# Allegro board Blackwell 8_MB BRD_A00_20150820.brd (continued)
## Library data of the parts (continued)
RAM1 RAM2 = BGA253G110115H38: tolerance: 072.H9CCN.000U
RT5101-RT5103 = NTC-402H22-U: tolerance: 69.60011.271
RTC1 SPK1 = 50281-0020N-001: tolerance: 20.F1530.002
SH1 = SKT1603X1424-24: tolerance: 434.05Y08.0001
SH2 = SKT951X1419-24-S: tolerance: 434.05Y0Z.0001
SH4 = SKT520X1447-24: tolerance: 434.05Y0X.0001
SH5 = SKT560X460-24: tolerance: 434.05Y0V.0001
SPR1-SPR3 = SPR5128H111: tolerance: 34.4YW18.001
SPR4 = SPR4013-1H75: tolerance: 34.16M01.001
TP1 = 51651-01001-001: tolerance: 020.K0147.0010
TP401 TP601 TP701 TP702 TP801-TP805 TP1601 TP1602 TP1707 TP1711-TP1713 TP1715 TP1717 TP1719 TP1720 TP2001 TP2401 TP2905-TP2910 TP2912 TP2913 TP2916 TP2918 TP2919 TP3001-TP3003 TP3005 TP3006 TP3901-TP3903 TP4002 TP4101 TP4501-TP4506 TP5101-TP5113 TP5401-TP5405 TP5601 TP5602 = TPAD14-OP: tolerance: ZZ.PAD14.001
U701 U1706 U1708-U1710 U2501 U3402 U4002 U4302 U4501 U4901 U5706 U5709 = SC70-6H44: tolerance: 84.UM6K1.B3F
U1702 U1707 U4301 = XSON8-1410H20: tolerance: 73.00102.A21
U1703 U1705 U5101 = CSP4J076H20: tolerance: 74.70533.03Z
U1704 = BGA169D1111H56: tolerance: 071.01633.000U
U2001 = QFN48J6-G465H40: tolerance: 071.05672.0003
U2901 = BGA96G60-1H40: tolerance: 074.65982.007Z
U2903 = DFN8A5060-G435345H32: tolerance: 72.25Q16.K01
U3101 = QFN28-G4121H32: tolerance: 071.03460.0003
U3102 = QFN48-G5D8H40: tolerance: 71.75130.003
U3401 U3403 = DFN4G1216-GD91D55H24: tolerance: 74.32402.093
U4101 = QFN20-G1D75H24: tolerance: 74.09500.0B3
U4401 = QFN24G4-G2D8H32: tolerance: 74.08556.AE3
U4602 = SSOIC8H44: tolerance: 73.01G74.0HB
U4603 = SC70-5H44: tolerance: 74.00348.A1F
U5202 = QFN10G2020-1H32: tolerance: 074.07066.0073
U5401 = DFN6G1D5H32: tolerance: 074.0G601.0073
U5407 = QFN24-G2D25H40: tolerance: 71.02232.003
U5702 = QFN32G5-G3D6H32: tolerance: 071.00650.0A03
U5707 U5708 = DFN10G2510H22: tolerance: 075.01043.0073
WC3708 = C0201H13: tolerance: 78.2R2B2.1SLRL
WC3710 = C0201H13: tolerance: 78.3R374.1SL
WU3701 = LGA100G1612-G8PH75: tolerance: 054.03042.0001
X701 = S-OSC4-2520-3H40: tolerance: 082.30001.0101
X703 X1701 = SMD49-3215-0713H36: tolerance: 082.30003.0221
XDP1 = AXT340124: tolerance: 20.F1412.040

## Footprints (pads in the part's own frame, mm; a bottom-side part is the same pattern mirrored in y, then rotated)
0R0201-PAD
  custom 0.076x0.076 smd: 1(0,0.279) 2(0,-0.279)
0R0402-PAD
  custom 0.127x0.127 smd: 1(0,0.432) 2(0,-0.432)
0R0603-PAD-1-U
  custom 0.254x0.254 smd: 1(0,0.66) 2(0,-0.66)
2SJ3108-028111F
  oval 1.27x2.032 hole 0.61x1.321: 1(-4.5,7.6) 2(-4.5,2.6) 6(4.5,2.4) MS(4.5,5)
  oval 1.27x1.854 hole 0.61x1.321: 3(-4.5,0) 4(4.5,0)
  oval 1.27x1.93 hole 0.61x1.219: 5(4.5,8.15)
20449-001E
  rect 0.61x0.559 smd: 1(0,-0.971)
  rect 0.508x0.508 smd: 2(0,0.996)
  rect 0.584x1.575 smd: 3(-0.958,0) 4(0.958,0)
50281-0020N-001
  rect 0.813x1.448 smd: 1(0.625,4.124) 2(-0.625,4.124)
  rect 1.346x1.6 smd: 3(2.525,0) 4(-2.525,0)
50521-01001-001
  rect 0.305x0.813 smd: 1(2.25,2.5) 2(1.75,2.5) 3(1.25,2.5) 4(0.75,2.5) 5(0.25,2.5) 6(-0.25,2.5) 7(-0.75,2.5) 8(-1.25,2.5) 9(-1.75,2.5) 10(-2.25,2.5)
  rect 0.406x0.813 smd: 11(3.25,0) 12(-3.25,0)
51483-00801-001
  rect 0.813x1.905 smd: 1(-4.375,4.925) 2(-3.125,4.925) 3(-1.875,4.925) 4(-0.625,4.925) 5(0.625,4.925) 6(1.875,4.925) 7(3.125,4.925) 8(4.375,4.925)
  rect 1.295x3.353 smd: 9(-7.225,0) 10(7.225,0)
51548-01541-W01
  rect 0.305x1.295 smd: 1(-3.5,3.05) 2(-3,3.05) 3(-2.5,3.05) 4(-2,3.05) 5(-1.5,3.05) 6(-1,3.05) 7(-0.5,3.05) 8(0,3.05) 9(0.5,3.05) 10(1,3.05) 11(1.5,3.05) 12(2,3.05) 13(2.5,3.05) 14(3,3.05) 15(3.5,3.05)
  rect 2.159x2.21 smd: 16(-5.825,0) 17(5.825,0)
51651-01001-001
  rect 0.305x0.813 smd: 1(-2.25,2.5) 2(-1.75,2.5) 3(-1.25,2.5) 4(-0.75,2.5) 5(-0.25,2.5) 6(0.25,2.5) 7(0.75,2.5) 8(1.25,2.5) 9(1.75,2.5) 10(2.25,2.5)
  rect 0.457x0.813 smd: 11(-3.465,0) 12(3.465,0)
503398-0891
  rect 0.711x1.092 smd: 1(-3.21,0.015) 2(-2.11,0.015) 3(-1.01,0.015) 4(0.09,0.015) 5(1.19,0.015) 6(2.29,0.015) 7(3.39,0.015) 8(4.49,0.015)
  rect 1.143x1.829 smd: 9(-7.089,0)
  rect 0.711x3.327 smd: 10(-7.305,-11.252) 13(5.644,-11.252)
  rect 0.889x0.94 smd: 11(-5,-12.445)
  rect 1.041x0.787 smd: 12(-0.739,-12.522)
  rect 0.864x2.794 smd: 14(5.568,-0.483)
AA077
  rect 0.508x1.6 smd: 1(-1.55,0) 2(1.55,0)
AS0BC56-R15BB-7H-U
  round 0.254 hole 1.168 unplated: (-11,0)
  round 0.254 hole 1.651 unplated: (11,0)
  round 0.711 hole 0.457: 1(9.25,-0.5) 3(8.75,-1.3) 5(8.25,-0.5) 7(7.75,-1.3) 9(7.25,-0.5) 11(6.75,-1.3) 21(4.25,-0.5) 23(3.75,-1.3) 25(3.25,-0.5) 27(2.75,-1.3) 29(2.25,-0.5) 31(1.75,-1.3) 33(1.25,-0.5) 35(0.75,-1.3) 37(0.25,-0.5) 39(-0.25,-1.3) 41(-0.75,-0.5) 43(-1.25,-1.3) 45(-1.75,-0.5) 47(-2.25,-1.3) 49(-2.75,-0.5) 51(-3.25,-1.3) 53(-3.75,-0.5) 55(-4.25,-1.3) 57(-4.75,-0.5) 59(-5.25,-1.3) 61(-5.75,-0.5) 63(-6.25,-1.3) 65(-6.75,-0.5) 67(-7.25,-1.3) 69(-7.75,-0.5) 71(-8.25,-1.3) 73(-8.75,-0.5) 75(-9.25,-1.3)
  rect 0.305x1.499 smd: 2(9,1.55) 4(8.5,1.55) 6(8,1.55) 8(7.5,1.55) 10(7,1.55) 20(4.5,1.55) 22(4,1.55) 24(3.5,1.55) 26(3,1.55) 28(2.5,1.55) 30(2,1.55) 32(1.5,1.55) 34(1,1.55) 36(0.5,1.55) 38(0,1.55) 40(-0.5,1.55) 42(-1,1.55) 44(-1.5,1.55) 46(-2,1.55) 48(-2.5,1.55) 50(-3,1.55) 52(-3.5,1.55) 54(-4,1.55) 56(-4.5,1.55) 58(-5,1.55) 60(-5.5,1.55) 62(-6,1.55) 64(-6.5,1.55) 66(-7,1.55) 68(-7.5,1.55) 70(-8,1.55) 72(-8.5,1.55) 74(-9,1.55)
  rect 1.194x2.743 smd: 76(-11.385,-4.97) 77(11.385,-4.97)
AXT340124
  rect 0.203x0.737 smd: 1(3.8,1.668) 2(3.8,-1.668) 3(3.4,1.668) 4(3.4,-1.668) 5(3,1.668) 6(3,-1.668) 7(2.6,1.668) 8(2.6,-1.668) 9(2.2,1.668) 10(2.2,-1.668) 11(1.8,1.668) 12(1.8,-1.668) 13(1.4,1.668) 14(1.4,-1.668) 15(1,1.668) 16(1,-1.668) 17(0.6,1.668) 18(0.6,-1.668) 19(0.2,1.668) 20(0.2,-1.668) 21(-0.2,1.668) 22(-0.2,-1.668) 23(-0.6,1.668) 24(-0.6,-1.668) 25(-1,1.668) 26(-1,-1.668) 27(-1.4,1.668) 28(-1.4,-1.668) 29(-1.8,1.668) 30(-1.8,-1.668) 31(-2.2,1.668) 32(-2.2,-1.668) 33(-2.6,1.668) 34(-2.6,-1.668) 35(-3,1.668) 36(-3,-1.668) 37(-3.4,1.668) 38(-3.4,-1.668) 39(-3.8,1.668) 40(-3.8,-1.668)
  rect 0.711x1.118 smd: 41(4.75,1.459) 42(4.75,-1.459) 43(-4.75,1.459) 44(-4.75,-1.459)
BGA96G60-1H40
  round 0.356 smd: A1(-2.5,2.5) A2(-2,2.5) A3(-1.5,2.5) A4(-1,2.5) A5(-0.5,2.5) A6(0,2.5) A7(0.5,2.5) A8(1,2.5) A9(1.5,2.5) A10(2,2.5) A11(2.5,2.5) B1(-2.5,2) B2(-2,2) B3(-1.5,2) B4(-1,2) B5(-0.5,2) B6(0,2) B7(0.5,2) B8(1,2) B9(1.5,2) B10(2,2) B11(2.5,2) C1(-2.5,1.5) C2(-2,1.5) C10(2,1.5) C11(2.5,1.5) D1(-2.5,1) D2(-2,1) D5(-0.5,1) D6(0,1) D7(0.5,1) D8(1,1) D10(2,1) D11(2.5,1) E1(-2.5,0.5) E2(-2,0.5) E4(-1,0.5) E5(-0.5,0.5) E6(0,0.5) E7(0.5,0.5) E8(1,0.5) E10(2,0.5) E11(2.5,0.5) F1(-2.5,0) F2(-2,0) F4(-1,0) F5(-0.5,0) F6(0,0) F7(0.5,0) F8(1,0) F10(2,0) F11(2.5,0) G1(-2.5,-0.5) G2(-2,-0.5) G4(-1,-0.5) G5(-0.5,-0.5) G6(0,-0.5) G7(0.5,-0.5) G8(1,-0.5) G10(2,-0.5) G11(2.5,-0.5) H1(-2.5,-1) H2(-2,-1) H4(-1,-1) H5(-0.5,-1) H6(0,-1) H7(0.5,-1) H8(1,-1) H10(2,-1) H11(2.5,-1) J1(-2.5,-1.5) J2(-2,-1.5) J10(2,-1.5) J11(2.5,-1.5) K1(-2.5,-2) K2(-2,-2) K3(-1.5,-2) K4(-1,-2) K5(-0.5,-2) K6(0,-2) K7(0.5,-2) K8(1,-2) K9(1.5,-2) K10(2,-2) K11(2.5,-2) L1(-2.5,-2.5) L2(-2,-2.5) L3(-1.5,-2.5) L4(-1,-2.5) L5(-0.5,-2.5) L6(0,-2.5) L7(0.5,-2.5) L8(1,-2.5) L9(1.5,-2.5) L10(2,-2.5) L11(2.5,-2.5)
BGA153G115130-1H40
  round 0.356 smd: A1(-3.25,3.25) A2(-2.75,3.25) A3(-2.25,3.25) A4(-1.75,3.25) A5(-1.25,3.25) A6(-0.75,3.25) A7(-0.25,3.25) A8(0.25,3.25) A9(0.75,3.25) A10(1.25,3.25) A11(1.75,3.25) A12(2.25,3.25) A13(2.75,3.25) A14(3.25,3.25) B1(-3.25,2.75) B2(-2.75,2.75) B3(-2.25,2.75) B4(-1.75,2.75) B5(-1.25,2.75) B6(-0.75,2.75) B7(-0.25,2.75) B8(0.25,2.75) B9(0.75,2.75) B10(1.25,2.75) B11(1.75,2.75) B12(2.25,2.75) B13(2.75,2.75) B14(3.25,2.75) C1(-3.25,2.25) C2(-2.75,2.25) C3(-2.25,2.25) C4(-1.75,2.25) C5(-1.25,2.25) C6(-0.75,2.25) C7(-0.25,2.25) C8(0.25,2.25) C9(0.75,2.25) C10(1.25,2.25) C11(1.75,2.25) C12(2.25,2.25) C13(2.75,2.25) C14(3.25,2.25) D1(-3.25,1.75) D2(-2.75,1.75) D3(-2.25,1.75) D4(-1.75,1.75) D12(2.25,1.75) D13(2.75,1.75) D14(3.25,1.75) E1(-3.25,1.25) E2(-2.75,1.25) E3(-2.25,1.25) E5(-1.25,1.25) E6(-0.75,1.25) E7(-0.25,1.25) E8(0.25,1.25) E9(0.75,1.25) E10(1.25,1.25) E12(2.25,1.25) E13(2.75,1.25) E14(3.25,1.25) F1(-3.25,0.75) F2(-2.75,0.75) F3(-2.25,0.75) F5(-1.25,0.75) F10(1.25,0.75) F12(2.25,0.75) F13(2.75,0.75) F14(3.25,0.75) G1(-3.25,0.25) G2(-2.75,0.25) G3(-2.25,0.25) G5(-1.25,0.25) G10(1.25,0.25) G12(2.25,0.25) G13(2.75,0.25) G14(3.25,0.25) H1(-3.25,-0.25) H2(-2.75,-0.25) H3(-2.25,-0.25) H5(-1.25,-0.25) H10(1.25,-0.25) H12(2.25,-0.25) H13(2.75,-0.25) H14(3.25,-0.25) J1(-3.25,-0.75) J2(-2.75,-0.75) J3(-2.25,-0.75) J5(-1.25,-0.75) J10(1.25,-0.75) J12(2.25,-0.75) J13(2.75,-0.75) J14(3.25,-0.75) K1(-3.25,-1.25) K2(-2.75,-1.25) K3(-2.25,-1.25) K5(-1.25,-1.25) K6(-0.75,-1.25) K7(-0.25,-1.25) K8(0.25,-1.25) K9(0.75,-1.25) K10(1.25,-1.25) K12(2.25,-1.25) K13(2.75,-1.25) K14(3.25,-1.25) L1(-3.25,-1.75) L2(-2.75,-1.75) L3(-2.25,-1.75) L12(2.25,-1.75) L13(2.75,-1.75) L14(3.25,-1.75) M1(-3.25,-2.25) M2(-2.75,-2.25) M3(-2.25,-2.25) M4(-1.75,-2.25) M5(-1.25,-2.25) M6(-0.75,-2.25) M7(-0.25,-2.25) M8(0.25,-2.25) M9(0.75,-2.25) M10(1.25,-2.25) M11(1.75,-2.25) M12(2.25,-2.25) M13(2.75,-2.25) M14(3.25,-2.25) N1(-3.25,-2.75) N2(-2.75,-2.75) N3(-2.25,-2.75) N4(-1.75,-2.75) N5(-1.25,-2.75) N6(-0.75,-2.75) N7(-0.25,-2.75) N8(0.25,-2.75) N9(0.75,-2.75) N10(1.25,-2.75) N11(1.75,-2.75) N12(2.25,-2.75) N13(2.75,-2.75) N14(3.25,-2.75) P1(-3.25,-3.25) P2(-2.75,-3.25) P3(-2.25,-3.25) P4(-1.75,-3.25) P5(-1.25,-3.25) P6(-0.75,-3.25) P7(-0.25,-3.25) P8(0.25,-3.25) P9(0.75,-3.25) P10(1.25,-3.25) P11(1.75,-3.25) P12(2.25,-3.25) P13(2.75,-3.25) P14(3.25,-3.25)
BGA169D1111H56
  round 0.406 smd: A1(-4.8,4.8) A2(-4,4.8) A3(-3.2,4.8) A11(3.2,4.8) A12(4,4.8) A13(4.8,4.8) B1(-4.8,4) B2(-4,4) B3(-3.2,4) B11(3.2,4) B12(4,4) B13(4.8,4) C1(-4.8,3.2) C2(-4,3.2) C3(-3.2,3.2) C11(3.2,3.2) C12(4,3.2) C13(4.8,3.2) L1(-4.8,-3.2) L2(-4,-3.2) L3(-3.2,-3.2) L11(3.2,-3.2) L12(4,-3.2) L13(4.8,-3.2) M1(-4.8,-4) M2(-4,-4) M3(-3.2,-4) M11(3.2,-4) M12(4,-4) M13(4.8,-4) N1(-4.8,-4.8) N2(-4,-4.8) N3(-3.2,-4.8) N11(3.2,-4.8) N12(4,-4.8) N13(4.8,-4.8)
  round 0.356 smd: A4(-2.4,4.8) A5(-1.6,4.8) A6(-0.8,4.8) A7(0,4.8) A8(0.8,4.8) A9(1.6,4.8) A10(2.4,4.8) B4(-2.4,4) B5(-1.6,4) B6(-0.8,4) B7(0,4) B8(0.8,4) B9(1.6,4) B10(2.4,4) C4(-2.4,3.2) C5(-1.6,3.2) C6(-0.8,3.2) C7(0,3.2) C8(0.8,3.2) C9(1.6,3.2) C10(2.4,3.2) D1(-4.8,2.4) D2(-4,2.4) D3(-3.2,2.4) D4(-2.4,2.4) D5(-1.6,2.4) D6(-0.8,2.4) D7(0,2.4) D8(0.8,2.4) D9(1.6,2.4) D10(2.4,2.4) D11(3.2,2.4) D12(4,2.4) D13(4.8,2.4) E1(-4.8,1.6) E2(-4,1.6) E3(-3.2,1.6) E4(-2.4,1.6) E5(-1.6,1.6) E6(-0.8,1.6) E7(0,1.6) E8(0.8,1.6) E9(1.6,1.6) E10(2.4,1.6) E11(3.2,1.6) E12(4,1.6) E13(4.8,1.6) F1(-4.8,0.8) F2(-4,0.8) F3(-3.2,0.8) F4(-2.4,0.8) F5(-1.6,0.8) F6(-0.8,0.8) F7(0,0.8) F8(0.8,0.8) F9(1.6,0.8) F10(2.4,0.8) F11(3.2,0.8) F12(4,0.8) F13(4.8,0.8) G1(-4.8,0) G2(-4,0) G3(-3.2,0) G4(-2.4,0) G5(-1.6,0) G6(-0.8,0) G7(0,0) G8(0.8,0) G9(1.6,0) G10(2.4,0) G11(3.2,0) G12(4,0) G13(4.8,0) H1(-4.8,-0.8) H2(-4,-0.8) H3(-3.2,-0.8) H4(-2.4,-0.8) H5(-1.6,-0.8) H6(-0.8,-0.8) H7(0,-0.8) H8(0.8,-0.8) H9(1.6,-0.8) H10(2.4,-0.8) H11(3.2,-0.8) H12(4,-0.8) H13(4.8,-0.8) J1(-4.8,-1.6) J2(-4,-1.6) J3(-3.2,-1.6) J4(-2.4,-1.6) J5(-1.6,-1.6) J6(-0.8,-1.6) J7(0,-1.6) J8(0.8,-1.6) J9(1.6,-1.6) J10(2.4,-1.6) J11(3.2,-1.6) J12(4,-1.6) J13(4.8,-1.6) K1(-4.8,-2.4) K2(-4,-2.4) K3(-3.2,-2.4) K4(-2.4,-2.4) K5(-1.6,-2.4) K6(-0.8,-2.4) K7(0,-2.4) K8(0.8,-2.4) K9(1.6,-2.4) K10(2.4,-2.4) K11(3.2,-2.4) K12(4,-2.4) K13(4.8,-2.4) L4(-2.4,-3.2) L5(-1.6,-3.2) L6(-0.8,-3.2) L7(0,-3.2) L8(0.8,-3.2) L9(1.6,-3.2) L10(2.4,-3.2) M4(-2.4,-4) M5(-1.6,-4) M6(-0.8,-4) M7(0,-4) M8(0.8,-4) M9(1.6,-4) M10(2.4,-4) N4(-2.4,-4.8) N5(-1.6,-4.8) N6(-0.8,-4.8) N7(0,-4.8) N8(0.8,-4.8) N9(1.6,-4.8) N10(2.4,-4.8)
BGA224J6D2H25
  round 0.241 smd: A1(-2.8,2.8) A2(-2.4,2.8) A3(-2,2.8) A4(-1.6,2.8) A5(-1.2,2.8) A6(-0.8,2.8) A7(-0.4,2.8) A8(0,2.8) A9(0.4,2.8) A10(0.8,2.8) A11(1.2,2.8) A12(1.6,2.8) A13(2,2.8) A14(2.4,2.8) A15(2.8,2.8) B1(-2.8,2.4) B2(-2.4,2.4) B3(-2,2.4) B4(-1.6,2.4) B5(-1.2,2.4) B6(-0.8,2.4) B7(-0.4,2.4) B8(0,2.4) B9(0.4,2.4) B10(0.8,2.4) B11(1.2,2.4) B12(1.6,2.4) B13(2,2.4) B14(2.4,2.4) B15(2.8,2.4) C1(-2.8,2) C2(-2.4,2) C3(-2,2) C4(-1.6,2) C5(-1.2,2) C6(-0.8,2) C7(-0.4,2) C8(0,2) C9(0.4,2) C10(0.8,2) C11(1.2,2) C12(1.6,2) C13(2,2) C14(2.4,2) C15(2.8,2) D1(-2.8,1.6) D2(-2.4,1.6) D3(-2,1.6) D4(-1.6,1.6) D5(-1.2,1.6) D6(-0.8,1.6) D7(-0.4,1.6) D8(0,1.6) D9(0.4,1.6) D10(0.8,1.6) D11(1.2,1.6) D12(1.6,1.6) D13(2,1.6) D14(2.4,1.6) D15(2.8,1.6) E1(-2.8,1.2) E2(-2.4,1.2) E3(-2,1.2) E4(-1.6,1.2) E5(-1.2,1.2) E6(-0.8,1.2) E7(-0.4,1.2) E8(0,1.2) E9(0.4,1.2) E10(0.8,1.2) E11(1.2,1.2) E12(1.6,1.2) E13(2,1.2) E14(2.4,1.2) E15(2.8,1.2) F1(-2.8,0.8) F2(-2.4,0.8) F3(-2,0.8) F4(-1.6,0.8) F5(-1.2,0.8) F6(-0.8,0.8) F7(-0.4,0.8) F8(0,0.8) F9(0.4,0.8) F10(0.8,0.8) F11(1.2,0.8) F12(1.6,0.8) F13(2,0.8) F14(2.4,0.8) F15(2.8,0.8) G1(-2.8,0.4) G2(-2.4,0.4) G3(-2,0.4) G4(-1.6,0.4) G5(-1.2,0.4) G6(-0.8,0.4) G8(0,0.4) G9(0.4,0.4) G10(0.8,0.4) G11(1.2,0.4) G12(1.6,0.4) G13(2,0.4) G14(2.4,0.4) G15(2.8,0.4) H1(-2.8,0) H2(-2.4,0) H3(-2,0) H4(-1.6,0) H5(-1.2,0) H6(-0.8,0) H7(-0.4,0) H8(0,0) H9(0.4,0) H10(0.8,0) H11(1.2,0) H12(1.6,0) H13(2,0) H14(2.4,0) H15(2.8,0) J1(-2.8,-0.4) J2(-2.4,-0.4) J3(-2,-0.4) J4(-1.6,-0.4) J5(-1.2,-0.4) J6(-0.8,-0.4) J7(-0.4,-0.4) J8(0,-0.4) J9(0.4,-0.4) J10(0.8,-0.4) J11(1.2,-0.4) J12(1.6,-0.4) J13(2,-0.4) J14(2.4,-0.4) J15(2.8,-0.4) K1(-2.8,-0.8) K2(-2.4,-0.8) K3(-2,-0.8) K4(-1.6,-0.8) K5(-1.2,-0.8) K6(-0.8,-0.8) K7(-0.4,-0.8) K8(0,-0.8) K9(0.4,-0.8) K10(0.8,-0.8) K11(1.2,-0.8) K12(1.6,-0.8) K13(2,-0.8) K14(2.4,-0.8) K15(2.8,-0.8) L1(-2.8,-1.2) L2(-2.4,-1.2) L3(-2,-1.2) L4(-1.6,-1.2) L5(-1.2,-1.2) L6(-0.8,-1.2) L7(-0.4,-1.2) L8(0,-1.2) L9(0.4,-1.2) L10(0.8,-1.2) L11(1.2,-1.2) L12(1.6,-1.2) L13(2,-1.2) L14(2.4,-1.2) L15(2.8,-1.2) M1(-2.8,-1.6) M2(-2.4,-1.6) M3(-2,-1.6) M4(-1.6,-1.6) M5(-1.2,-1.6) M6(-0.8,-1.6) M7(-0.4,-1.6) M8(0,-1.6) M9(0.4,-1.6) M10(0.8,-1.6) M11(1.2,-1.6) M12(1.6,-1.6) M13(2,-1.6) M14(2.4,-1.6) M15(2.8,-1.6) N1(-2.8,-2) N2(-2.4,-2) N3(-2,-2) N4(-1.6,-2) N5(-1.2,-2) N6(-0.8,-2) N7(-0.4,-2) N8(0,-2) N9(0.4,-2) N10(0.8,-2) N11(1.2,-2) N12(1.6,-2) N13(2,-2) N14(2.4,-2) N15(2.8,-2) P1(-2.8,-2.4) P2(-2.4,-2.4) P3(-2,-2.4) P4(-1.6,-2.4) P5(-1.2,-2.4) P6(-0.8,-2.4) P7(-0.4,-2.4) P8(0,-2.4) P9(0.4,-2.4) P10(0.8,-2.4) P11(1.2,-2.4) P12(1.6,-2.4) P13(2,-2.4) P14(2.4,-2.4) P15(2.8,-2.4) R1(-2.8,-2.8) R2(-2.4,-2.8) R3(-2,-2.8) R4(-1.6,-2.8) R5(-1.2,-2.8) R6(-0.8,-2.8) R7(-0.4,-2.8) R8(0,-2.8) R9(0.4,-2.8) R10(0.8,-2.8) R11(1.2,-2.8) R12(1.6,-2.8) R13(2,-2.8) R14(2.4,-2.8) R15(2.8,-2.8)
BGA253G110115H38
  round 0.356 smd: A1(-4,4) A2(-3.5,4) A3(-3,4) A4(-2.5,4) A5(-2,4) A6(-1.5,4) A7(-1,4) A8(-0.5,4) A9(0,4) A10(0.5,4) A11(1,4) A12(1.5,4) A13(2,4) A14(2.5,4) A15(3,4) A16(3.5,4) A17(4,4) B1(-4,3.5) B2(-3.5,3.5) B3(-3,3.5) B4(-2.5,3.5) B5(-2,3.5) B6(-1.5,3.5) B7(-1,3.5) B8(-0.5,3.5) B9(0,3.5) B10(0.5,3.5) B11(1,3.5) B12(1.5,3.5) B13(2,3.5) B14(2.5,3.5) B15(3,3.5) B16(3.5,3.5) B17(4,3.5) C1(-4,3) C2(-3.5,3) C3(-3,3) C4(-2.5,3) C5(-2,3) C6(-1.5,3) C7(-1,3) C8(-0.5,3) C9(0,3) C10(0.5,3) C11(1,3) C12(1.5,3) C13(2,3) C14(2.5,3) C15(3,3) C16(3.5,3) C17(4,3) D1(-4,2.5) D2(-3.5,2.5) D3(-3,2.5) D4(-2.5,2.5) D5(-2,2.5) D6(-1.5,2.5) D7(-1,2.5) D8(-0.5,2.5) D9(0,2.5) D10(0.5,2.5) D11(1,2.5) D12(1.5,2.5) D13(2,2.5) D14(2.5,2.5) D15(3,2.5) D16(3.5,2.5) D17(4,2.5) E1(-4,2) E2(-3.5,2) E3(-3,2) E4(-2.5,2) E5(-2,2) E6(-1.5,2) E7(-1,2) E8(-0.5,2) E9(0,2) E10(0.5,2) E11(1,2) E12(1.5,2) E13(2,2) E14(2.5,2) E15(3,2) E16(3.5,2) E17(4,2) F1(-4,1.5) F2(-3.5,1.5) F3(-3,1.5) F4(-2.5,1.5) F5(-2,1.5) F12(1.5,1.5) F13(2,1.5) F14(2.5,1.5) F15(3,1.5) F16(3.5,1.5) F17(4,1.5) G1(-4,1) G2(-3.5,1) G3(-3,1) G4(-2.5,1) G5(-2,1) G12(1.5,1) G13(2,1) G14(2.5,1) G15(3,1) G16(3.5,1) G17(4,1) H1(-4,0.5) H2(-3.5,0.5) H3(-3,0.5) H4(-2.5,0.5) H5(-2,0.5) H12(1.5,0.5) H13(2,0.5) H14(2.5,0.5) H15(3,0.5) H16(3.5,0.5) H17(4,0.5) J1(-4,0) J2(-3.5,0) J3(-3,0) J4(-2.5,0) J5(-2,0) J12(1.5,0) J13(2,0) J14(2.5,0) J15(3,0) J16(3.5,0) J17(4,0) K1(-4,-0.5) K2(-3.5,-0.5) K3(-3,-0.5) K4(-2.5,-0.5) K5(-2,-0.5) K12(1.5,-0.5) K13(2,-0.5) K14(2.5,-0.5) K15(3,-0.5) K16(3.5,-0.5) K17(4,-0.5) L1(-4,-1) L2(-3.5,-1) L3(-3,-1) L4(-2.5,-1) L5(-2,-1) L12(1.5,-1) L13(2,-1) L14(2.5,-1) L15(3,-1) L16(3.5,-1) L17(4,-1) M1(-4,-1.5) M2(-3.5,-1.5) M3(-3,-1.5) M4(-2.5,-1.5) M5(-2,-1.5) M6(-1.5,-1.5) M7(-1,-1.5) M8(-0.5,-1.5) M9(0,-1.5) M10(0.5,-1.5) M11(1,-1.5) M12(1.5,-1.5) M13(2,-1.5) M14(2.5,-1.5) M15(3,-1.5) M16(3.5,-1.5) M17(4,-1.5) N1(-4,-2) N2(-3.5,-2) N3(-3,-2) N4(-2.5,-2) N5(-2,-2) N6(-1.5,-2) N7(-1,-2) N8(-0.5,-2) N9(0,-2) N10(0.5,-2) N11(1,-2) N12(1.5,-2) N13(2,-2) N14(2.5,-2) N15(3,-2) N16(3.5,-2) N17(4,-2) P1(-4,-2.5) P2(-3.5,-2.5) P3(-3,-2.5) P4(-2.5,-2.5) P5(-2,-2.5) P6(-1.5,-2.5) P7(-1,-2.5) P8(-0.5,-2.5) P9(0,-2.5) P10(0.5,-2.5) P11(1,-2.5) P12(1.5,-2.5) P13(2,-2.5) P14(2.5,-2.5) P15(3,-2.5) P16(3.5,-2.5) P17(4,-2.5) R1(-4,-3) R2(-3.5,-3) R3(-3,-3) R4(-2.5,-3) R5(-2,-3) R6(-1.5,-3) R7(-1,-3) R8(-0.5,-3) R9(0,-3) R10(0.5,-3) R11(1,-3) R12(1.5,-3) R13(2,-3) R14(2.5,-3) R15(3,-3) R16(3.5,-3) R17(4,-3) T1(-4,-3.5) T2(-3.5,-3.5) T3(-3,-3.5) T4(-2.5,-3.5) T5(-2,-3.5) T6(-1.5,-3.5) T7(-1,-3.5) T8(-0.5,-3.5) T9(0,-3.5) T10(0.5,-3.5) T11(1,-3.5) T12(1.5,-3.5) T13(2,-3.5) T14(2.5,-3.5) T15(3,-3.5) T16(3.5,-3.5) T17(4,-3.5) U1(-4,-4) U2(-3.5,-4) U3(-3,-4) U4(-2.5,-4) U5(-2,-4) U6(-1.5,-4) U7(-1,-4) U8(-0.5,-4) U9(0,-4) U10(0.5,-4) U11(1,-4) U12(1.5,-4) U13(2,-4) U14(2.5,-4) U15(3,-4) U16(3.5,-4) U17(4,-4)
BGA1380M17-UH41
  round 0.25 smd: A3(7.357,-7.998) A5(6.791,-7.998) A7(6.225,-7.998) A53(-6.225,-7.998) A55(-6.791,-7.998) A57(-7.357,-7.998) AA3(7.357,-2.264) AA5(6.791,-2.264) AA7(6.225,-2.264) AA9(5.659,-2.264) AA11(5.093,-2.264) AA49(-5.093,-2.264) AA51(-5.659,-2.264) AA53(-6.225,-2.264) AA55(-6.791,-2.264) AA57(-7.357,-2.264) AB4(7.074,-1.981) AB6(6.508,-1.981) AB8(5.942,-1.981) AB10(5.376,-1.981) AB12(4.81,-1.981) AB48(-4.81,-1.981) AB50(-5.376,-1.981) AB52(-5.942,-1.981) AB54(-6.508,-1.981) AB56(-7.074,-1.981) AC3(7.357,-1.698) AC5(6.791,-1.698) AC7(6.225,-1.698) AC9(5.659,-1.698) AC11(5.093,-1.698) AC49(-5.093,-1.698) AC51(-5.659,-1.698) AC53(-6.225,-1.698) AC55(-6.791,-1.698) AC57(-7.357,-1.698) AD2(7.715,-1.415) AD4(7.074,-1.415) AD6(6.508,-1.415) AD8(5.942,-1.415) AD10(5.376,-1.415) AD12(4.81,-1.415) AD48(-4.81,-1.415) AD50(-5.376,-1.415) AD52(-5.942,-1.415) AD54(-6.508,-1.415) AD56(-7.074,-1.415) AD58(-7.715,-1.415) AE3(7.394,-1.169) AE5(6.791,-1.132) AE7(6.225,-1.132) AE9(5.659,-1.132) AE11(5.093,-1.132) AE49(-5.093,-1.132) AE51(-5.659,-1.132) AE53(-6.225,-1.132) AE55(-6.791,-1.132) AE57(-7.394,-1.169) AF4(7.074,-0.849) AF6(6.508,-0.849) AF8(5.942,-0.849) AF10(5.376,-0.849) AF12(4.81,-0.849) AF48(-4.81,-0.849) AF50(-5.376,-0.849) AF52(-5.942,-0.849) AF54(-6.508,-0.849) AF56(-7.074,-0.849) AG3(7.394,-0.529) AG5(6.791,-0.566) AG7(6.225,-0.566) AG9(5.659,-0.566) AG11(5.093,-0.566) AG49(-5.093,-0.566) AG51(-5.659,-0.566) AG53(-6.225,-0.566) AG55(-6.791,-0.566) AG57(-7.394,-0.529) AH2(7.715,-0.283) AH4(7.074,-0.283) AH6(6.508,-0.283) AH8(5.942,-0.283) AH10(5.376,-0.283) AH12(4.81,-0.283) AH48(-4.81,-0.283) AH50(-5.376,-0.283) AH52(-5.942,-0.283) AH54(-6.508,-0.283) AH56(-7.074,-0.283) AH58(-7.715,-0.283) AK3(7.357,0) AK5(6.791,0) AK7(6.225,0) AK9(5.659,0) AK11(5.093,0) AK49(-5.093,0) AK51(-5.659,0) AK53(-6.225,0) AK55(-6.791,0) AK57(-7.357,0) AM2(7.715,0.283) AM4(7.074,0.283) AM6(6.508,0.283) AM8(5.942,0.283) AM10(5.376,0.283) AM12(4.81,0.283) AM48(-4.81,0.283) AM50(-5.376,0.283) AM52(-5.942,0.283) AM54(-6.508,0.283) AM56(-7.074,0.283) AM58(-7.715,0.283) AN3(7.394,0.529) AN5(6.791,0.566) AN7(6.225,0.566) AN9(5.659,0.566) AN11(5.093,0.566) AN49(-5.093,0.566) AN51(-5.659,0.566) AN53(-6.225,0.566) AN55(-6.791,0.566) AN57(-7.394,0.529) AP4(7.074,0.849) AP6(6.508,0.849) AP8(5.942,0.849) AP10(5.376,0.849) AP12(4.81,0.849) AP48(-4.81,0.849) AP50(-5.376,0.849) AP52(-5.942,0.849) AP54(-6.508,0.849) AP56(-7.074,0.849) AR3(7.394,1.169) AR5(6.791,1.132) AR7(6.225,1.132) AR9(5.659,1.132) AR11(5.093,1.132) AR49(-5.093,1.132) AR51(-5.659,1.132) AR53(-6.225,1.132) AR55(-6.791,1.132) AR57(-7.394,1.169) AT2(7.715,1.415) AT4(7.074,1.415) AT6(6.508,1.415) AT8(5.942,1.415) AT10(5.376,1.415) AT12(4.81,1.415) AT48(-4.81,1.415) AT50(-5.376,1.415) AT52(-5.942,1.415) AT54(-6.508,1.415) AT56(-7.074,1.415) AT58(-7.715,1.415) AU3(7.357,1.698) AU5(6.791,1.698) AU7(6.225,1.698) AU9(5.659,1.698) AU11(5.093,1.698) AU49(-5.093,1.698) AU51(-5.659,1.698) AU53(-6.225,1.698) AU55(-6.791,1.698) AU57(-7.357,1.698) AV4(7.074,1.981) AV6(6.508,1.981) AV8(5.942,1.981) AV10(5.376,1.981) AV12(4.81,1.981) AV48(-4.81,1.981) AV50(-5.376,1.981) AV52(-5.942,1.981) AV54(-6.508,1.981) AV56(-7.074,1.981) AW3(7.357,2.264) AW5(6.791,2.264) AW7(6.225,2.264) AW9(5.659,2.264) AW11(5.093,2.264) AW49(-5.093,2.264) AW51(-5.659,2.264) AW53(-6.225,2.264) AW55(-6.791,2.264) AW57(-7.357,2.264) AY2(7.715,2.547) AY4(7.074,2.547) AY6(6.508,2.547) AY8(5.942,2.547) AY10(5.376,2.547) AY12(4.81,2.547) AY48(-4.81,2.547) AY50(-5.376,2.547) AY52(-5.942,2.547) AY54(-6.508,2.547) AY56(-7.074,2.547) AY58(-7.715,2.547) B2(7.64,-7.64) B4(7.074,-7.715) B6(6.508,-7.64) B8(5.942,-7.715) B12(4.81,-7.715) B16(3.678,-7.715) B20(2.547,-7.715) B24(1.415,-7.715) B28(0.283,-7.715) B34(-0.849,-7.715) B38(-1.981,-7.715) B42(-3.113,-7.715) B46(-4.244,-7.715) B50(-5.376,-7.715) B54(-6.508,-7.715) B56(-7.074,-7.64) B58(-7.64,-7.64) BA3(7.394,2.792) BA5(6.791,2.83) BA7(6.225,2.83) BA9(5.659,2.83) BA11(5.093,2.83) BA49(-5.093,2.83) BA51(-5.659,2.83) BA53(-6.225,2.83) BA55(-6.791,2.83) BA57(-7.394,2.792) BB4(7.074,3.113) BB6(6.508,3.113) BB8(5.942,3.113) BB10(5.376,3.113) BB12(4.81,3.113) BB48(-4.81,3.113) BB50(-5.376,3.113) BB52(-5.942,3.113) BB54(-6.508,3.113) BB56(-7.074,3.113) BC3(7.394,3.433) BC5(6.791,3.395) BC7(6.225,3.395) BC9(5.659,3.395) BC11(5.093,3.395) BC49(-5.093,3.395) BC51(-5.659,3.395) BC53(-6.225,3.395) BC55(-6.791,3.395) BC57(-7.394,3.433) BD2(7.715,3.678) BD4(7.074,3.678) BD6(6.508,3.678) BD8(5.942,3.678) BD10(5.376,3.678) BD12(4.81,3.678) BD48(-4.81,3.678) BD50(-5.376,3.678) BD52(-5.942,3.678) BD54(-6.508,3.678) BD56(-7.074,3.678) BD58(-7.715,3.678) BE3(7.357,3.961) BE5(6.791,3.961) BE7(6.225,3.961) BE9(5.659,3.961) BE11(5.093,3.961) BE49(-5.093,3.961) BE51(-5.659,3.961) BE53(-6.225,3.961) BE55(-6.791,3.961) BE57(-7.357,3.961) BF4(7.074,4.244) BF6(6.508,4.244) BF8(5.942,4.244) BF10(5.376,4.244) BF12(4.81,4.244) BF48(-4.81,4.244) BF50(-5.376,4.244) BF52(-5.942,4.244) BF54(-6.508,4.244) BF56(-7.074,4.244) BG3(7.357,4.527) BG5(6.791,4.527) BG7(6.225,4.527) BG9(5.659,4.527) BG11(5.093,4.527) BG49(-5.093,4.527) BG51(-5.659,4.527) BG53(-6.225,4.527) BG55(-6.791,4.527) BG57(-7.357,4.527) BH2(7.715,4.81) BH4(7.074,4.81) BH6(6.508,4.81) BH8(5.942,4.81) BH10(5.376,4.81) BH12(4.81,4.81) BH14(4.244,4.81) BH16(3.678,4.81) BH18(3.113,4.81) BH20(2.547,4.81) BH22(1.981,4.81) BH24(1.415,4.81) BH26(0.849,4.81) BH28(0.283,4.81) BH32(-0.283,4.81) BH34(-0.849,4.81) BH36(-1.415,4.81) BH38(-1.981,4.81) BH40(-2.547,4.81) BH42(-3.113,4.81) BH44(-3.678,4.81) BH46(-4.244,4.81) BH48(-4.81,4.81) BH50(-5.376,4.81) BH52(-5.942,4.81) BH54(-6.508,4.81) BH56(-7.074,4.81) BH58(-7.715,4.81) BJ3(7.394,5.056) BJ5(6.791,5.093) BJ7(6.225,5.093) BJ9(5.659,5.093) BJ11(5.093,5.093) BJ13(4.527,5.093) BJ15(3.961,5.093) BJ17(3.395,5.093) BJ19(2.83,5.093) BJ21(2.264,5.093) BJ23(1.698,5.093) BJ25(1.132,5.093) BJ27(0.566,5.093) BJ30(0,5.093) BJ33(-0.566,5.093) BJ35(-1.132,5.093) BJ37(-1.698,5.093) BJ39(-2.264,5.093) BJ41(-2.83,5.093) BJ43(-3.395,5.093) BJ45(-3.961,5.093) BJ47(-4.527,5.093) BJ49(-5.093,5.093) BJ51(-5.659,5.093) BJ53(-6.225,5.093) BJ55(-6.791,5.093) BJ57(-7.394,5.056) BK4(7.074,5.376) BK6(6.508,5.376) BK8(5.942,5.376) BK10(5.376,5.376) BK12(4.81,5.376) BK14(4.244,5.376) BK16(3.678,5.376) BK18(3.113,5.376) BK20(2.547,5.376) BK22(1.981,5.376) BK24(1.415,5.376) BK26(0.849,5.376) BK28(0.283,5.376) BK32(-0.283,5.376) BK34(-0.849,5.376) BK36(-1.415,5.376) BK38(-1.981,5.376) BK40(-2.547,5.376) BK42(-3.113,5.376) BK44(-3.678,5.376) BK46(-4.244,5.376) BK48(-4.81,5.376) BK50(-5.376,5.376) BK52(-5.942,5.376) BK54(-6.508,5.376) BK56(-7.074,5.376) BL3(7.394,5.696) BL5(6.791,5.659) BL7(6.225,5.659) BL9(5.659,5.659) BL11(5.093,5.659) BL13(4.527,5.659) BL15(3.961,5.659) BL17(3.395,5.659) BL19(2.83,5.659) BL21(2.264,5.659) BL23(1.698,5.659) BL25(1.132,5.659) BL27(0.566,5.659) BL30(0,5.659) BL33(-0.566,5.659) BL35(-1.132,5.659) BL37(-1.698,5.659) BL39(-2.264,5.659) BL41(-2.83,5.659) BL43(-3.395,5.659) BL45(-3.961,5.659) BL47(-4.527,5.659) BL49(-5.093,5.659) BL51(-5.659,5.659) BL53(-6.225,5.659) BL55(-6.791,5.659) BL57(-7.394,5.696) BM2(7.715,5.942) BM4(7.074,5.942) BM6(6.508,5.942) BM8(5.942,5.942) BM10(5.376,5.942) BM12(4.81,5.942) BM14(4.244,5.942) BM16(3.678,5.942) BM18(3.113,5.942) BM20(2.547,5.942) BM22(1.981,5.942) BM24(1.415,5.942) BM26(0.849,5.942) BM28(0.283,5.942) BM32(-0.283,5.942) BM34(-0.849,5.942) BM36(-1.415,5.942) BM38(-1.981,5.942) BM40(-2.547,5.942) BM42(-3.113,5.942) BM44(-3.678,5.942) BM46(-4.244,5.942) BM48(-4.81,5.942) BM50(-5.376,5.942) BM52(-5.942,5.942) BM54(-6.508,5.942) BM56(-7.074,5.942) BM58(-7.715,5.942) BN1(7.998,6.225) BN3(7.357,6.225) BN5(6.791,6.225) BN7(6.225,6.225) BN9(5.659,6.225) BN11(5.093,6.225) BN13(4.527,6.225) BN15(3.961,6.225) BN17(3.395,6.225) BN19(2.83,6.225) BN21(2.264,6.225) BN23(1.698,6.225) BN25(1.132,6.225) BN27(0.566,6.225) BN30(0,6.225) BN33(-0.566,6.225) BN35(-1.132,6.225) BN37(-1.698,6.225) BN39(-2.264,6.225) BN41(-2.83,6.225) BN43(-3.395,6.225) BN45(-3.961,6.225) BN47(-4.527,6.225) BN49(-5.093,6.225) BN51(-5.659,6.225) BN53(-6.225,6.225) BN55(-6.791,6.225) BN57(-7.357,6.225) BN59(-7.998,6.225) BP2(7.64,6.508) BP4(7.074,6.508) BP6(6.508,6.508) BP8(5.942,6.508) BP10(5.376,6.508) BP12(4.81,6.508) BP14(4.244,6.508) BP16(3.678,6.508) BP18(3.113,6.508) BP20(2.547,6.508) BP22(1.981,6.508) BP24(1.415,6.508) BP26(0.849,6.508) BP28(0.283,6.508) BP32(-0.283,6.508) BP34(-0.849,6.508) BP36(-1.415,6.508) BP38(-1.981,6.508) BP40(-2.547,6.508) BP42(-3.113,6.508) BP44(-3.678,6.508) BP46(-4.244,6.508) BP48(-4.81,6.508) BP50(-5.376,6.508) BP52(-5.942,6.508) BP54(-6.508,6.508) BP56(-7.074,6.508) BP58(-7.64,6.508) BR1(7.998,6.791) BR3(7.357,6.791) BR5(6.791,6.791) BR7(6.225,6.791) BR9(5.659,6.791) BR11(5.093,6.791) BR13(4.527,6.791) BR15(3.961,6.791) BR17(3.395,6.791) BR19(2.83,6.791) BR21(2.264,6.791) BR23(1.698,6.791) BR25(1.132,6.791) BR27(0.566,6.791) BR30(0,6.791) BR33(-0.566,6.791) BR35(-1.132,6.791) BR37(-1.698,6.791) BR39(-2.264,6.791) BR41(-2.83,6.791) BR43(-3.395,6.791) BR45(-3.961,6.791) BR47(-4.527,6.791) BR49(-5.093,6.791) BR51(-5.659,6.791) BR53(-6.225,6.791) BR55(-6.791,6.791) BR57(-7.357,6.791) BR59(-7.998,6.791) BT2(7.715,7.074) BT4(7.074,7.074) BT6(6.508,7.074) BT8(5.942,7.074) BT10(5.376,7.074) BT12(4.81,7.074) BT14(4.244,7.074) BT16(3.678,7.074) BT18(3.113,7.074) BT20(2.547,7.074) BT22(1.981,7.074) BT24(1.415,7.074) BT26(0.849,7.074) BT28(0.283,7.074) BT32(-0.283,7.074) BT34(-0.849,7.074) BT36(-1.415,7.074) BT38(-1.981,7.074) BT40(-2.547,7.074) BT42(-3.113,7.074) BT44(-3.678,7.074) BT46(-4.244,7.074) BT48(-4.81,7.074) BT50(-5.376,7.074) BT52(-5.942,7.074) BT54(-6.508,7.074) BT56(-7.074,7.074) BT58(-7.715,7.074) BU1(7.998,7.357) BU3(7.357,7.357) BU5(6.791,7.357) BU7(6.225,7.357) BU9(5.696,7.394) BU11(5.056,7.394) BU13(4.527,7.357) BU15(3.961,7.357) BU17(3.433,7.394) BU19(2.792,7.394) BU21(2.264,7.357) BU23(1.698,7.357) BU25(1.169,7.394) BU27(0.529,7.394) BU30(0,7.357) BU33(-0.603,7.394) BU35(-1.132,7.357) BU37(-1.698,7.357) BU39(-2.227,7.394) BU41(-2.867,7.394) BU43(-3.395,7.357) BU45(-3.961,7.357) BU47(-4.49,7.394) BU49(-5.13,7.394) BU51(-5.659,7.357) BU53(-6.225,7.357) BU55(-6.791,7.357) BU57(-7.394,7.32) BU59(-7.998,7.357) BV2(7.64,7.64) BV4(7.074,7.715) BV6(6.508,7.64) BV8(5.942,7.715) BV12(4.81,7.715) BV16(3.678,7.715) BV20(2.547,7.715) BV24(1.415,7.715) BV28(0.283,7.715) BV34(-0.849,7.715) BV38(-1.981,7.715) BV42(-3.113,7.715) BV46(-4.244,7.715) BV50(-5.376,7.715) BV54(-6.508,7.715) BV56(-7.074,7.64) BV58(-7.64,7.64) BW3(7.357,7.998) BW5(6.791,7.998) BW7(6.225,7.998) BW53(-6.225,7.998) BW55(-6.791,7.998) BW57(-7.357,7.998) C1(7.998,-7.357) C3(7.357,-7.357) C5(6.791,-7.357) C7(6.225,-7.357) C9(5.696,-7.394) C11(5.056,-7.394) C13(4.527,-7.357) C15(3.961,-7.357) C17(3.433,-7.394) C19(2.792,-7.394) C21(2.264,-7.357) C23(1.698,-7.357) C25(1.169,-7.394) C27(0.529,-7.394) C30(0,-7.357) C33(-0.603,-7.394) C35(-1.132,-7.357) C37(-1.698,-7.357) C39(-2.227,-7.394) C41(-2.867,-7.394) C43(-3.395,-7.357) C45(-3.961,-7.357) C47(-4.49,-7.394) C49(-5.13,-7.394) C51(-5.659,-7.357) C53(-6.225,-7.357) C55(-6.791,-7.357) C57(-7.394,-7.32) C59(-7.998,-7.357) D2(7.715,-7.074) D4(7.074,-7.074) D6(6.508,-7.074) D8(5.942,-7.074) D10(5.376,-7.074) D12(4.81,-7.074) D14(4.244,-7.074) D16(3.678,-7.074) D18(3.113,-7.074) D20(2.547,-7.074) D22(1.981,-7.074) D24(1.415,-7.074) D26(0.849,-7.074) D28(0.283,-7.074) D32(-0.283,-7.074) D34(-0.849,-7.074) D36(-1.415,-7.074) D38(-1.981,-7.074) D40(-2.547,-7.074) D42(-3.113,-7.074) D44(-3.678,-7.074) D46(-4.244,-7.074) D48(-4.81,-7.074) D50(-5.376,-7.074) D52(-5.942,-7.074) D54(-6.508,-7.074) D56(-7.074,-7.074) D58(-7.715,-7.074) E1(7.998,-6.791) E3(7.357,-6.791) E5(6.791,-6.791) E7(6.225,-6.791) E9(5.659,-6.791) E11(5.093,-6.791) E13(4.527,-6.791) E15(3.961,-6.791) E17(3.395,-6.791) E19(2.83,-6.791) E21(2.264,-6.791) E23(1.698,-6.791) E25(1.132,-6.791) E27(0.566,-6.791) E30(0,-6.791) E33(-0.566,-6.791) E35(-1.132,-6.791) E37(-1.698,-6.791) E39(-2.264,-6.791) E41(-2.83,-6.791) E43(-3.395,-6.791) E45(-3.961,-6.791) E47(-4.527,-6.791) E49(-5.093,-6.791) E51(-5.659,-6.791) E53(-6.225,-6.791) E55(-6.791,-6.791) E57(-7.357,-6.791) E59(-7.998,-6.791) F2(7.64,-6.508) F4(7.074,-6.508) F6(6.508,-6.508) F8(5.942,-6.508) F10(5.376,-6.508) F12(4.81,-6.508) F14(4.244,-6.508) F16(3.678,-6.508) F18(3.113,-6.508) F20(2.547,-6.508) F22(1.981,-6.508) F24(1.415,-6.508) F26(0.849,-6.508) F28(0.283,-6.508) F32(-0.283,-6.508) F34(-0.849,-6.508) F36(-1.415,-6.508) F38(-1.981,-6.508) F40(-2.547,-6.508) F42(-3.113,-6.508) F44(-3.678,-6.508) F46(-4.244,-6.508) F48(-4.81,-6.508) F50(-5.376,-6.508) F52(-5.942,-6.508) F54(-6.508,-6.508) F56(-7.074,-6.508) F58(-7.64,-6.508) G1(7.998,-6.225) G3(7.357,-6.225) G5(6.791,-6.225) G7(6.225,-6.225) G9(5.659,-6.225) G11(5.093,-6.225) G13(4.527,-6.225) G15(3.961,-6.225) G17(3.395,-6.225) G19(2.83,-6.225) G21(2.264,-6.225) G23(1.698,-6.225) G25(1.132,-6.225) G27(0.566,-6.225) G30(0,-6.225) G33(-0.566,-6.225) G35(-1.132,-6.225) G37(-1.698,-6.225) G39(-2.264,-6.225) G41(-2.83,-6.225) G43(-3.395,-6.225) G45(-3.961,-6.225) G47(-4.527,-6.225) G49(-5.093,-6.225) G51(-5.659,-6.225) G53(-6.225,-6.225) G55(-6.791,-6.225) G57(-7.357,-6.225) G59(-7.998,-6.225) H2(7.715,-5.942) H4(7.074,-5.942) H6(6.508,-5.942) H8(5.942,-5.942) H10(5.376,-5.942) H12(4.81,-5.942) H14(4.244,-5.942) H16(3.678,-5.942) H18(3.113,-5.942) H20(2.547,-5.942) H22(1.981,-5.942) H24(1.415,-5.942) H26(0.849,-5.942) H28(0.283,-5.942) H32(-0.283,-5.942) H34(-0.849,-5.942) H36(-1.415,-5.942) H38(-1.981,-5.942) H40(-2.547,-5.942) H42(-3.113,-5.942) H44(-3.678,-5.942) H46(-4.244,-5.942) H48(-4.81,-5.942) H50(-5.376,-5.942) H52(-5.942,-5.942) H54(-6.508,-5.942) H56(-7.074,-5.942) H58(-7.715,-5.942) J3(7.394,-5.696) J5(6.791,-5.659) J7(6.225,-5.659) J9(5.659,-5.659) J11(5.093,-5.659) J13(4.527,-5.659) J15(3.961,-5.659) J17(3.395,-5.659) J19(2.83,-5.659) J21(2.264,-5.659) J23(1.698,-5.659) J25(1.132,-5.659) J27(0.566,-5.659) J30(0,-5.659) J33(-0.566,-5.659) J35(-1.132,-5.659) J37(-1.698,-5.659) J39(-2.264,-5.659) J41(-2.83,-5.659) J43(-3.395,-5.659) J45(-3.961,-5.659) J47(-4.527,-5.659) J49(-5.093,-5.659) J51(-5.659,-5.659) J53(-6.225,-5.659) J55(-6.791,-5.659) J57(-7.394,-5.696) K4(7.074,-5.376) K6(6.508,-5.376) K8(5.942,-5.376) K10(5.376,-5.376) K12(4.81,-5.376) K14(4.244,-5.376) K16(3.678,-5.376) K18(3.113,-5.376) K20(2.547,-5.376) K22(1.981,-5.376) K24(1.415,-5.376) K26(0.849,-5.376) K28(0.283,-5.376) K32(-0.283,-5.376) K34(-0.849,-5.376) K36(-1.415,-5.376) K38(-1.981,-5.376) K40(-2.547,-5.376) K42(-3.113,-5.376) K44(-3.678,-5.376) K46(-4.244,-5.376) K48(-4.81,-5.376) K50(-5.376,-5.376) K52(-5.942,-5.376) K54(-6.508,-5.376) K56(-7.074,-5.376) L3(7.394,-5.056) L5(6.791,-5.093) L7(6.225,-5.093) L9(5.659,-5.093) L11(5.093,-5.093) L13(4.527,-5.093) L15(3.961,-5.093) L17(3.395,-5.093) L19(2.83,-5.093) L21(2.264,-5.093) L23(1.698,-5.093) L25(1.132,-5.093) L27(0.566,-5.093) L30(0,-5.093) L33(-0.566,-5.093) L35(-1.132,-5.093) L37(-1.698,-5.093) L39(-2.264,-5.093) L41(-2.83,-5.093) L43(-3.395,-5.093) L45(-3.961,-5.093) L47(-4.527,-5.093) L49(-5.093,-5.093) L51(-5.659,-5.093) L53(-6.225,-5.093) L55(-6.791,-5.093) L57(-7.394,-5.056) M2(7.715,-4.81) M4(7.074,-4.81) M6(6.508,-4.81) M8(5.942,-4.81) M10(5.376,-4.81) M12(4.81,-4.81) M14(4.244,-4.81) M16(3.678,-4.81) M18(3.113,-4.81) M20(2.547,-4.81) M22(1.981,-4.81) M24(1.415,-4.81) M26(0.849,-4.81) M28(0.283,-4.81) M32(-0.283,-4.81) M34(-0.849,-4.81) M36(-1.415,-4.81) M38(-1.981,-4.81) M40(-2.547,-4.81) M42(-3.113,-4.81) M44(-3.678,-4.81) M46(-4.244,-4.81) M48(-4.81,-4.81) M50(-5.376,-4.81) M52(-5.942,-4.81) M54(-6.508,-4.81) M56(-7.074,-4.81) M58(-7.715,-4.81) N3(7.357,-4.527) N5(6.791,-4.527) N7(6.225,-4.527) N9(5.659,-4.527) N11(5.093,-4.527) N49(-5.093,-4.527) N51(-5.659,-4.527) N53(-6.225,-4.527) N55(-6.791,-4.527) N57(-7.357,-4.527) P4(7.074,-4.244) P6(6.508,-4.244) P8(5.942,-4.244) P10(5.376,-4.244) P12(4.81,-4.244) P48(-4.81,-4.244) P50(-5.376,-4.244) P52(-5.942,-4.244) P54(-6.508,-4.244) P56(-7.074,-4.244) R3(7.357,-3.961) R5(6.791,-3.961) R7(6.225,-3.961) R9(5.659,-3.961) R11(5.093,-3.961) R49(-5.093,-3.961) R51(-5.659,-3.961) R53(-6.225,-3.961) R55(-6.791,-3.961) R57(-7.357,-3.961) T2(7.715,-3.678) T4(7.074,-3.678) T6(6.508,-3.678) T8(5.942,-3.678) T10(5.376,-3.678) T12(4.81,-3.678) T48(-4.81,-3.678) T50(-5.376,-3.678) T52(-5.942,-3.678) T54(-6.508,-3.678) T56(-7.074,-3.678) T58(-7.715,-3.678) U3(7.394,-3.433) U5(6.791,-3.395) U7(6.225,-3.395) U9(5.659,-3.395) U11(5.093,-3.395) U49(-5.093,-3.395) U51(-5.659,-3.395) U53(-6.225,-3.395) U55(-6.791,-3.395) U57(-7.394,-3.433) V4(7.074,-3.113) V6(6.508,-3.113) V8(5.942,-3.113) V10(5.376,-3.113) V12(4.81,-3.113) V48(-4.81,-3.113) V50(-5.376,-3.113) V52(-5.942,-3.113) V54(-6.508,-3.113) V56(-7.074,-3.113) W3(7.394,-2.792) W5(6.791,-2.83) W7(6.225,-2.83) W9(5.659,-2.83) W11(5.093,-2.83) W49(-5.093,-2.83) W51(-5.659,-2.83) W53(-6.225,-2.83) W55(-6.791,-2.83) W57(-7.394,-2.792) Y2(7.715,-2.547) Y4(7.074,-2.547) Y6(6.508,-2.547) Y8(5.942,-2.547) Y10(5.376,-2.547) Y12(4.81,-2.547) Y48(-4.81,-2.547) Y50(-5.376,-2.547) Y52(-5.942,-2.547) Y54(-6.508,-2.547) Y56(-7.074,-2.547) Y58(-7.715,-2.547)
  round 0.33 smd: A9(5.659,-7.998) A11(5.093,-7.998) A13(4.527,-7.998) A15(3.961,-7.998) A17(3.395,-7.998) A19(2.83,-7.998) A21(2.264,-7.998) A23(1.698,-7.998) A25(1.132,-7.998) A27(0.566,-7.998) A30(0,-7.998) A33(-0.566,-7.998) A35(-1.132,-7.998) A37(-1.698,-7.998) A39(-2.264,-7.998) A41(-2.83,-7.998) A43(-3.395,-7.998) A45(-3.961,-7.998) A47(-4.527,-7.998) A49(-5.093,-7.998) A51(-5.659,-7.998) AA1(7.998,-2.264) AA59(-7.998,-2.264) AB2(7.64,-1.981) AB58(-7.64,-1.981) AC1(7.998,-1.698) AC59(-7.998,-1.698) AE1(7.998,-1.132) AE59(-7.998,-1.132) AF2(7.64,-0.849) AF58(-7.64,-0.849) AG1(7.998,-0.566) AG59(-7.998,-0.566) AK1(7.998,0) AK59(-7.998,0) AN1(7.998,0.566) AN59(-7.998,0.566) AP2(7.64,0.849) AP58(-7.64,0.849) AR1(7.998,1.132) AR59(-7.998,1.132) AU1(7.998,1.698) AU59(-7.998,1.698) AV2(7.64,1.981) AV58(-7.64,1.981) AW1(7.998,2.264) AW59(-7.998,2.264) B10(5.376,-7.64) B14(4.244,-7.64) B18(3.113,-7.64) B22(1.981,-7.64) B26(0.849,-7.64) B32(-0.283,-7.64) B36(-1.415,-7.64) B40(-2.547,-7.64) B44(-3.678,-7.64) B48(-4.81,-7.64) B52(-5.942,-7.64) BA1(7.998,2.83) BA59(-7.998,2.83) BB2(7.64,3.113) BB58(-7.64,3.113) BC1(7.998,3.395) BC59(-7.998,3.395) BE1(7.998,3.961) BE59(-7.998,3.961) BF2(7.64,4.244) BF58(-7.64,4.244) BG1(7.998,4.527) BG59(-7.998,4.527) BJ1(7.998,5.093) BJ59(-7.998,5.093) BK2(7.64,5.376) BK58(-7.64,5.376) BL1(7.998,5.659) BL59(-7.998,5.659) BV10(5.376,7.64) BV14(4.244,7.64) BV18(3.113,7.64) BV22(1.981,7.64) BV26(0.849,7.64) BV32(-0.283,7.64) BV36(-1.415,7.64) BV40(-2.547,7.64) BV44(-3.678,7.64) BV48(-4.81,7.64) BV52(-5.942,7.64) BW9(5.659,7.998) BW11(5.093,7.998) BW13(4.527,7.998) BW15(3.961,7.998) BW17(3.395,7.998) BW19(2.83,7.998) BW21(2.264,7.998) BW23(1.698,7.998) BW25(1.132,7.998) BW27(0.566,7.998) BW30(0,7.998) BW33(-0.566,7.998) BW35(-1.132,7.998) BW37(-1.698,7.998) BW39(-2.264,7.998) BW41(-2.83,7.998) BW43(-3.395,7.998) BW45(-3.961,7.998) BW47(-4.527,7.998) BW49(-5.093,7.998) BW51(-5.659,7.998) J1(7.998,-5.659) J59(-7.998,-5.659) K2(7.64,-5.376) K58(-7.64,-5.376) L1(7.998,-5.093) L59(-7.998,-5.093) N1(7.998,-4.527) N59(-7.998,-4.527) P2(7.64,-4.244) P58(-7.64,-4.244) R1(7.998,-3.961) R59(-7.998,-3.961) U1(7.998,-3.395) U59(-7.998,-3.395) V2(7.64,-3.113) V58(-7.64,-3.113) W1(7.998,-2.83) W59(-7.998,-2.83)
  round 0.279 smd: AA15(3.989,-2.383) AA17(3.439,-2.383) AA19(2.888,-2.383) AA21(2.338,-2.383) AA23(1.788,-2.383) AA25(1.238,-2.383) AA27(0.688,-2.383) AA29(0.137,-2.383) AA32(-0.413,-2.383) AA34(-0.963,-2.383) AA36(-1.513,-2.383) AA38(-2.063,-2.383) AA40(-2.614,-2.383) AA42(-3.164,-2.383) AA44(-3.714,-2.383) AA46(-4.264,-2.383) AC14(4.264,-1.906) AC16(3.714,-1.906) AC18(3.164,-1.906) AC20(2.613,-1.906) AC22(2.063,-1.906) AC24(1.513,-1.906) AC26(0.963,-1.906) AC28(0.412,-1.906) AC31(-0.138,-1.906) AC33(-0.688,-1.906) AC35(-1.238,-1.906) AC37(-1.788,-1.906) AC39(-2.339,-1.906) AC41(-2.889,-1.906) AC43(-3.439,-1.906) AC45(-3.989,-1.906) AD15(3.989,-1.43) AD17(3.439,-1.43) AD19(2.888,-1.43) AD21(2.338,-1.43) AD23(1.788,-1.43) AD25(1.238,-1.43) AD27(0.688,-1.43) AD29(0.137,-1.43) AD32(-0.413,-1.43) AD34(-0.963,-1.43) AD36(-1.513,-1.43) AD38(-2.063,-1.43) AD40(-2.614,-1.43) AD42(-3.164,-1.43) AD44(-3.714,-1.43) AD46(-4.264,-1.43) AF14(4.264,-0.953) AF16(3.714,-0.953) AF18(3.164,-0.953) AF20(2.613,-0.953) AF22(2.063,-0.953) AF24(1.513,-0.953) AF26(0.963,-0.953) AF28(0.412,-0.953) AF31(-0.138,-0.953) AF33(-0.688,-0.953) AF35(-1.238,-0.953) AF37(-1.788,-0.953) AF39(-2.339,-0.953) AF41(-2.889,-0.953) AF43(-3.439,-0.953) AF45(-3.989,-0.953) AH15(3.989,-0.477) AH17(3.439,-0.477) AH19(2.888,-0.477) AH21(2.338,-0.477) AH23(1.788,-0.477) AH25(1.238,-0.477) AH27(0.688,-0.477) AH29(0.137,-0.477) AH32(-0.413,-0.477) AH34(-0.963,-0.477) AH36(-1.513,-0.477) AH38(-2.063,-0.477) AH40(-2.614,-0.477) AH42(-3.164,-0.477) AH44(-3.714,-0.477) AH46(-4.264,-0.477) AK14(4.264,0) AK16(3.714,0) AK18(3.164,0) AK20(2.613,0) AK22(2.063,0) AK24(1.513,0) AK26(0.963,0) AK28(0.412,0) AK31(-0.138,0) AK33(-0.688,0) AK35(-1.238,0) AK37(-1.788,0) AK39(-2.339,0) AK41(-2.889,0) AK43(-3.439,0) AK45(-3.989,0) AM15(3.989,0.477) AM17(3.439,0.477) AM19(2.888,0.477) AM21(2.338,0.477) AM23(1.788,0.477) AM25(1.238,0.477) AM27(0.688,0.477) AM29(0.137,0.477) AM32(-0.413,0.477) AM34(-0.963,0.477) AM36(-1.513,0.477) AM38(-2.063,0.477) AM40(-2.614,0.477) AM42(-3.164,0.477) AM44(-3.714,0.477) AM46(-4.264,0.477) AP14(4.264,0.953) AP16(3.714,0.953) AP18(3.164,0.953) AP20(2.613,0.953) AP22(2.063,0.953) AP24(1.513,0.953) AP26(0.963,0.953) AP28(0.412,0.953) AP31(-0.138,0.953) AP33(-0.688,0.953) AP35(-1.238,0.953) AP37(-1.788,0.953) AP39(-2.339,0.953) AP41(-2.889,0.953) AP43(-3.439,0.953) AP45(-3.989,0.953) AT15(3.989,1.43) AT17(3.439,1.43) AT19(2.888,1.43) AT21(2.338,1.43) AT23(1.788,1.43) AT25(1.238,1.43) AT27(0.688,1.43) AT29(0.137,1.43) AT32(-0.413,1.43) AT34(-0.963,1.43) AT36(-1.513,1.43) AT38(-2.063,1.43) AT40(-2.614,1.43) AT42(-3.164,1.43) AT44(-3.714,1.43) AT46(-4.264,1.43) AU14(4.264,1.906) AU16(3.714,1.906) AU18(3.164,1.906) AU20(2.613,1.906) AU22(2.063,1.906) AU24(1.513,1.906) AU26(0.963,1.906) AU28(0.412,1.906) AU31(-0.138,1.906) AU33(-0.688,1.906) AU35(-1.238,1.906) AU37(-1.788,1.906) AU39(-2.339,1.906) AU41(-2.889,1.906) AU43(-3.439,1.906) AU45(-3.989,1.906) AW15(3.989,2.383) AW17(3.439,2.383) AW19(2.888,2.383) AW21(2.338,2.383) AW23(1.788,2.383) AW25(1.238,2.383) AW27(0.688,2.383) AW29(0.137,2.383) AW32(-0.413,2.383) AW34(-0.963,2.383) AW36(-1.513,2.383) AW38(-2.063,2.383) AW40(-2.614,2.383) AW42(-3.164,2.383) AW44(-3.714,2.383) AW46(-4.264,2.383) BA14(4.264,2.859) BA16(3.714,2.859) BA18(3.164,2.859) BA20(2.613,2.859) BA22(2.063,2.859) BA24(1.513,2.859) BA26(0.963,2.859) BA28(0.412,2.859) BA31(-0.138,2.859) BA33(-0.688,2.859) BA35(-1.238,2.859) BA37(-1.788,2.859) BA39(-2.339,2.859) BA41(-2.889,2.859) BA43(-3.439,2.859) BA45(-3.989,2.859) BB15(3.989,3.336) BB17(3.439,3.336) BB19(2.888,3.336) BB21(2.338,3.336) BB23(1.788,3.336) BB25(1.238,3.336) BB27(0.688,3.336) BB29(0.137,3.336) BB32(-0.413,3.336) BB34(-0.963,3.336) BB36(-1.513,3.336) BB38(-2.063,3.336) BB40(-2.614,3.336) BB42(-3.164,3.336) BB44(-3.714,3.336) BB46(-4.264,3.336) BD14(4.264,3.812) BD16(3.714,3.812) BD18(3.164,3.812) BD20(2.613,3.812) BD22(2.063,3.812) BD24(1.513,3.812) BD26(0.963,3.812) BD28(0.412,3.812) BD31(-0.138,3.812) BD33(-0.688,3.812) BD35(-1.238,3.812) BD37(-1.788,3.812) BD39(-2.339,3.812) BD41(-2.889,3.812) BD43(-3.439,3.812) BD45(-3.989,3.812) BF15(3.989,4.289) BF17(3.439,4.289) BF19(2.888,4.289) BF21(2.338,4.289) BF23(1.788,4.289) BF25(1.238,4.289) BF27(0.688,4.289) BF29(0.137,4.289) BF32(-0.413,4.289) BF34(-0.963,4.289) BF36(-1.513,4.289) BF38(-2.063,4.289) BF40(-2.614,4.289) BF42(-3.164,4.289) BF44(-3.714,4.289) BF46(-4.264,4.289) P15(3.989,-4.289) P17(3.439,-4.289) P19(2.888,-4.289) P21(2.338,-4.289) P23(1.788,-4.289) P25(1.238,-4.289) P27(0.688,-4.289) P29(0.137,-4.289) P32(-0.413,-4.289) P34(-0.963,-4.289) P36(-1.513,-4.289) P38(-2.063,-4.289) P40(-2.614,-4.289) P42(-3.164,-4.289) P44(-3.714,-4.289) P46(-4.264,-4.289) T14(4.264,-3.812) T16(3.714,-3.812) T18(3.164,-3.812) T20(2.613,-3.812) T22(2.063,-3.812) T24(1.513,-3.812) T26(0.963,-3.812) T28(0.412,-3.812) T31(-0.138,-3.812) T33(-0.688,-3.812) T35(-1.238,-3.812) T37(-1.788,-3.812) T39(-2.339,-3.812) T41(-2.889,-3.812) T43(-3.439,-3.812) T45(-3.989,-3.812) V15(3.989,-3.336) V17(3.439,-3.336) V19(2.888,-3.336) V21(2.338,-3.336) V23(1.788,-3.336) V25(1.238,-3.336) V27(0.688,-3.336) V29(0.137,-3.336) V32(-0.413,-3.336) V34(-0.963,-3.336) V36(-1.513,-3.336) V38(-2.063,-3.336) V40(-2.614,-3.336) V42(-3.164,-3.336) V44(-3.714,-3.336) V46(-4.264,-3.336) W14(4.264,-2.859) W16(3.714,-2.859) W18(3.164,-2.859) W20(2.613,-2.859) W22(2.063,-2.859) W24(1.513,-2.859) W26(0.963,-2.859) W28(0.412,-2.859) W31(-0.138,-2.859) W33(-0.688,-2.859) W35(-1.238,-2.859) W37(-1.788,-2.859) W39(-2.339,-2.859) W41(-2.889,-2.859) W43(-3.439,-2.859) W45(-3.989,-2.859)
C0201H13
  custom 0.076x0.076 smd: 1(0,0.279) 2(0,-0.279)
C0201H14
  custom 0.076x0.076 smd: 1(0,0.279) 2(0,-0.279)
C402-TO0D2H26
  custom 0.152x0.152 smd: 1(0,0.457) 2(0,-0.457)
C402-TO0D2H28
  custom 0.152x0.152 smd: 1(0,0.457) 2(0,-0.457)
C402H22
  custom 0.114x0.114 smd: 1(0,0.457) 2(0,-0.457)
C603H32
  custom 0.197x0.197 smd: 1(0,0.66) 2(0,-0.66)
C603H36
  custom 0.197x0.197 smd: 1(0,0.66) 2(0,-0.66)
C603H38
  custom 0.197x0.197 smd: 1(0,0.66) 2(0,-0.66)
C603H40
  custom 0.197x0.197 smd: 1(0,0.66) 2(0,-0.66)
C603H42
  custom 0.216x0.216 smd: 1(0,0.762) 2(0,-0.762)
CSP4J076H20
  round 0.241 smd: A1(-0.2,0.2) A2(0.2,0.2) B1(-0.2,-0.2) B2(0.2,-0.2)
D0201H13
  custom 0.076x0.076 smd: 1(0,0.279) 2(0,-0.279)
D402H18
  custom 0.127x0.127 smd: 1(0,0.432) 2(0,-0.432)
D1006-0304AKH16
  rect 0.61x0.584 smd: A(0,0.445) K(0,-0.445)
DF30FC-30DS
  rect 0.203x0.813 smd: 1(2.8,2.136) 2(2.4,2.136) 3(2,2.136) 4(1.6,2.136) 5(1.2,2.136) 6(0.8,2.136) 7(0.4,2.136) 8(0,2.136) 9(-0.4,2.136) 10(-0.8,2.136) 11(-1.2,2.136) 12(-1.6,2.136) 13(-2,2.136) 14(-2.4,2.136) 15(-2.8,2.136) 16(-2.8,-2.136) 17(-2.4,-2.136) 18(-2,-2.136) 19(-1.6,-2.136) 20(-1.2,-2.136) 21(-0.8,-2.136) 22(-0.4,-2.136) 23(0,-2.136) 24(0.4,-2.136) 25(0.8,-2.136) 26(1.2,-2.136) 27(1.6,-2.136) 28(2,-2.136) 29(2.4,-2.136) 30(2.8,-2.136)
DFN4G1216-GD91D55H24
  rect 0.305x0.559 smd: 1(0.25,0.775) 2(-0.25,0.775) 3(-0.25,-0.775) 4(0.25,-0.775)
  rect 0.914x0.508 smd: 5(0,0)
DFN6G1D5H32
  rect 0.305x0.94 smd: 1(0.5,0.534)
  rect 0.305x0.838 smd: 2(0,0.585) 3(-0.5,0.585) 4(-0.5,-0.585) 5(0,-0.585) 6(0.5,-0.585)
DFN8A5060-G435345H32
  rect 0.635x1.118 smd: 1(1.905,2.695) 2(0.635,2.695) 3(-0.635,2.695) 4(-1.905,2.695) 5(-1.905,-2.695) 6(-0.635,-2.695) 7(0.635,-2.695) 8(1.905,-2.695)
  rect 4.343x3.454 smd: 9(0,0)
DFN10G2510H22
  rect 0.305x0.66 smd: 1(1,0.43) 5(-1,0.43) 6(-1,-0.43) 10(1,-0.43)
  rect 0.254x0.66 smd: 2(0.521,0.43) 4(-0.521,0.43) 7(-0.521,-0.43) 9(0.521,-0.43)
  rect 0.025x0.025 smd: 3(0,0.43)
  rect 0.406x1.499 smd: 8(0,-0.43)
FH34SRJ-6S-0D5SH-50-U
  rect 0.305x0.813 smd: 1(1.25,2.5) 2(0.75,2.5) 3(0.25,2.5) 4(-0.25,2.5) 5(-0.75,2.5) 6(-1.25,2.5)
  rect 0.406x0.813 smd: 7(2.25,0) 8(-2.25,0)
FH35C-21S-0D3SHW-50
  rect 0.305x0.838 smd: 1(3,-0.298) 3(2.4,-0.298) 5(1.8,-0.298) 7(1.2,-0.298) 9(0.6,-0.298) 11(0,-0.298) 13(-0.6,-0.298) 15(-1.2,-0.298) 17(-1.8,-0.298) 19(-2.4,-0.298) 21(-3,-0.298)
  rect 0.305x0.686 smd: 2(2.7,2.623) 4(2.1,2.623) 6(1.5,2.623) 8(0.9,2.623) 10(0.3,2.623) 12(-0.3,2.623) 14(-0.9,2.623) 16(-1.5,2.623) 18(-2.1,2.623) 20(-2.7,2.623)
  rect 0.406x0.94 smd: 22(3.7,0) 23(-3.7,0)
FH35C-45S-0D3SHW-50-U
  rect 0.305x0.813 smd: 1(6.6,-0.275) 3(6,-0.275) 5(5.4,-0.275) 7(4.8,-0.275) 9(4.2,-0.275) 11(3.6,-0.275) 13(3,-0.275) 15(2.4,-0.275) 17(1.8,-0.275) 19(1.2,-0.275) 21(0.6,-0.275) 23(0,-0.275) 25(-0.6,-0.275) 27(-1.2,-0.275) 29(-1.8,-0.275) 31(-2.4,-0.275) 33(-3,-0.275) 35(-3.6,-0.275) 37(-4.2,-0.275) 39(-4.8,-0.275) 41(-5.4,-0.275) 43(-6,-0.275) 45(-6.6,-0.275)
  rect 0.305x0.66 smd: 2(6.3,2.6) 4(5.7,2.6) 6(5.1,2.6) 8(4.5,2.6) 10(3.9,2.6) 12(3.3,2.6) 14(2.7,2.6) 16(2.1,2.6) 18(1.5,2.6) 20(0.9,2.6) 22(0.3,2.6) 24(-0.3,2.6) 26(-0.9,2.6) 28(-1.5,2.6) 30(-2.1,2.6) 32(-2.7,2.6) 34(-3.3,2.6) 36(-3.9,2.6) 38(-4.5,2.6) 40(-5.1,2.6) 42(-5.7,2.6) 44(-6.3,2.6)
  rect 0.406x0.94 smd: 46(7.3,0) 47(-7.3,0)
GAP-CLOSE-PWR-3
  rect 0.66x0.762 smd: 1(-0.305,0) 2(0.305,0)
HOLE197R79
  round 5.004 hole 2.007: 1(0,0)
HOLE197R103
  round 5.004 hole 2.616: 1(0,0)
L2016-D516H40
  rect 1.854x1.016 smd: 1(0,0.754) 2(0,-0.754)
L2520-D620H48
  rect 2.261x1.118 smd: 1(0,0.955) 2(0,-0.955)
L4442-D820H48
  rect 2.515x1.676 smd: 1(0,1.857) 2(0,-1.857)
L6965-1330-UH60
  rect 3.505x2.184 smd: 1(0,2.846) 2(0,-2.846)
LD65D85-4PH20
  rect 0.457x0.559 smd: 1(0.354,0.377) 2(-0.354,0.377) 3(-0.354,-0.377) 4(0.354,-0.377)
LD85D65-4P-1H20
  rect 0.533x0.33 smd: 1(0.382,0.29) 2(0.382,-0.29) 3(-0.382,-0.29) 4(-0.382,0.29)
LED1608AKH20
  rect 1.067x0.813 smd: A(0,0.653) K(0,-0.653)
LED3020-3P-6H44
  rect 0.991x1.499 smd: 1(1.495,0) 3(-1.495,0)
  rect 0.889x0.889 smd: 2(0,-0.65)
LGA16-3030-H40
  rect 0.305x0.559 smd: 1(1,1.221) 2(0.5,1.221) 3(0,1.221) 4(-0.5,1.221) 5(-1,1.221) 9(-1,-1.221) 10(-0.5,-1.221) 11(0,-1.221) 12(0.5,-1.221) 13(1,-1.221)
  rect 0.559x0.305 smd: 6(-1.221,0.5) 7(-1.221,0) 8(-1.221,-0.5) 14(1.221,-0.5) 15(1.221,0) 16(1.221,0.5)
LGA100G1612-G8PH75
  rect 0.305x0.762 smd: 1(6.75,5.625) 2(6.25,5.625) 3(5.75,5.625) 4(5.25,5.625) 5(4.75,5.625) 6(4.25,5.625) 7(3.75,5.625) 8(3.25,5.625) 9(2.75,5.625) 10(2.25,5.625) 11(1.75,5.625) 12(1.25,5.625) 13(0.75,5.625) 14(0.25,5.625) 15(-0.25,5.625) 16(-0.75,5.625) 17(-1.25,5.625) 18(-1.75,5.625) 19(-2.25,5.625) 20(-2.75,5.625) 21(-3.25,5.625) 22(-3.75,5.625) 23(-4.25,5.625) 24(-4.75,5.625) 25(-5.25,5.625) 26(-5.75,5.625) 27(-6.25,5.625) 28(-6.75,5.625) 49(-6.75,-5.625) 50(-6.25,-5.625) 51(-5.75,-5.625) 52(-5.25,-5.625) 53(-4.75,-5.625) 54(-4.25,-5.625) 55(-3.75,-5.625) 56(-3.25,-5.625) 57(-2.75,-5.625) 58(-2.25,-5.625) 59(-1.75,-5.625) 60(-1.25,-5.625) 61(-0.75,-5.625) 62(-0.25,-5.625) 63(0.25,-5.625) 64(0.75,-5.625) 65(1.25,-5.625) 66(1.75,-5.625) 67(2.25,-5.625) 68(2.75,-5.625) 69(3.25,-5.625) 70(3.75,-5.625) 71(4.25,-5.625) 72(4.75,-5.625) 73(5.25,-5.625) 74(5.75,-5.625) 75(6.25,-5.625) 76(6.75,-5.625)
  rect 0.762x0.305 smd: 29(-7.625,4.75) 30(-7.625,4.25) 31(-7.625,3.75) 32(-7.625,3.25) 33(-7.625,2.75) 34(-7.625,2.25) 35(-7.625,1.75) 36(-7.625,1.25) 37(-7.625,0.75) 38(-7.625,0.25) 39(-7.625,-0.25) 40(-7.625,-0.75) 41(-7.625,-1.25) 42(-7.625,-1.75) 43(-7.625,-2.25) 44(-7.625,-2.75) 45(-7.625,-3.25) 46(-7.625,-3.75) 47(-7.625,-4.25) 48(-7.625,-4.75) 77(7.625,-4.75) 78(7.625,-4.25) 79(7.625,-3.75) 80(7.625,-3.25) 81(7.625,-2.75) 82(7.625,-2.25) 83(7.625,-1.75) 84(7.625,-1.25) 85(7.625,-0.75) 86(7.625,-0.25) 87(7.625,0.25) 88(7.625,0.75) 89(7.625,1.25) 90(7.625,1.75) 91(7.625,2.25) 92(7.625,2.75) 93(7.625,3.25) 94(7.625,3.75) 95(7.625,4.25) 96(7.625,4.75)
  rect 0.889x0.889 smd: G1(7.55,5.55) G2(-7.55,5.55) G3(-7.55,-5.55) G4(7.55,-5.55)
  rect 3.048x3.048 smd: G5(4.975,-1.675) G8(-4.975,-1.675) G9(4.975,1.675) G12(-4.975,1.675)
  rect 2.997x3.048 smd: G6(1.65,-1.675) G7(-1.65,-1.675) G10(1.65,1.675) G11(-1.65,1.675)
NTC-402H22-U
  custom 0.127x0.127 smd: 1(0,0.432) 2(0,-0.432)
PPAK-8P-2H45
  rect 0.406x1.041 smd: 1(-0.975,-2.22) 2(-0.325,-2.22) 3(0.325,-2.22) 4(0.975,-2.22)
  rect 3.404x2.642 smd: 5(0,0)
  rect 0.025x0.025 smd: 6(1.029,0.902) 7(0.013,0.902) 8(-0.991,0.902)
PPAK-8P-G5324H44-COLAY
  rect 0.762x0.889 smd: 1(-1.905,-2.946) 2(-0.635,-2.946) 3(0.635,-2.946) 4(1.905,-2.946) 5(1.905,2.946) 6(0.635,2.946) 7(-0.635,2.946) 8(-1.905,2.946)
  rect 5.207x2.896 smd: 9(0,0.65)
  rect 5.207x0.787 smd: 10(0,-1.7)
QFN10G2020-1H32
  rect 0.305x1.499 smd: 1(0.25,0.401) 2(-0.25,0.401) 3(-0.75,0.401)
  rect 0.305x0.559 smd: 4(-0.75,-0.871) 5(-0.25,-0.871) 6(0.25,-0.871)
  rect 0.508x0.305 smd: 7(0.86,-0.75) 8(0.86,-0.25) 9(0.86,0.25) 10(0.86,0.75)
QFN20-G1D75H24
  rect 0.203x0.66 smd: 1(0.8,1.487) 2(0.4,1.487) 3(0,1.487) 4(-0.4,1.487) 5(-0.8,1.487) 11(-0.8,-1.487) 12(-0.4,-1.487) 13(0,-1.487) 14(0.4,-1.487) 15(0.8,-1.487)
  rect 0.66x0.203 smd: 6(-1.487,0.8) 7(-1.487,0.4) 8(-1.487,0) 9(-1.487,-0.4) 10(-1.487,-0.8) 16(1.487,-0.8) 17(1.487,-0.4) 18(1.487,0) 19(1.487,0.4) 20(1.487,0.8)
  rect 1.753x1.753 smd: 21(0,0)
QFN24-G2D25H40
  rect 0.305x0.66 smd: 1(1.25,1.987) 6(-1.25,1.987) 13(-1.25,-1.987) 18(1.25,-1.987)
  rect 0.305x0.813 smd: 2(0.75,1.911) 3(0.25,1.911) 4(-0.25,1.911) 5(-0.75,1.911) 14(-0.75,-1.911) 15(-0.25,-1.911) 16(0.25,-1.911) 17(0.75,-1.911)
  rect 0.66x0.305 smd: 7(-1.987,1.25) 12(-1.987,-1.25) 19(1.987,-1.25) 24(1.987,1.25)
  rect 0.813x0.305 smd: 8(-1.911,0.75) 9(-1.911,0.25) 10(-1.911,-0.25) 11(-1.911,-0.75) 20(1.911,-0.75) 21(1.911,-0.25) 22(1.911,0.25) 23(1.911,0.75)
  rect 2.261x2.261 smd: 25(0,0)
